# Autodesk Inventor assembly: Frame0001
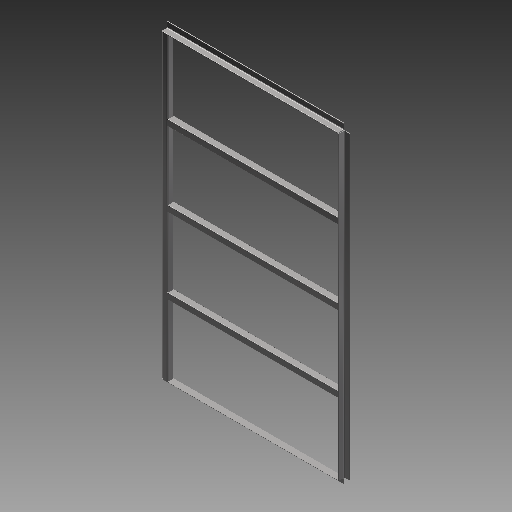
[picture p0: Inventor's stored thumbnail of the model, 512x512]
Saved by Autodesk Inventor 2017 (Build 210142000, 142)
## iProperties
Created: 2020-07
Part Number: Frame0001
Document SubType Name: Assembly
Designer: X
_FrameDoc: Frame Assembly
_Version: 15.0.0
Author: X
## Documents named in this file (16)
- C:\Users\WindowsX\Desktop\brama\skrzydlo_lewe\Frame\Frame0001.iam
- C:\Users\WindowsX\Desktop\brama\skrzydlo_lewe\Frame\Skeleton0001.ipt
- C:\Users\WindowsX\Desktop\brama\skrzydlo_lewe\Frame\PN L40x40x4 00000011.ipt
- PN L35x35x4 00000004.ipt
- C:\Users\WindowsX\Desktop\brama\skrzydlo_lewe\Frame\PN L40x40x4 00000012.ipt
- PN L35x35x4 00000002.ipt
- C:\Users\WindowsX\Desktop\brama\skrzydlo_lewe\Frame\PN L40x40x4 00000013.ipt
- PN L35x35x4 00000003.ipt
- C:\Users\WindowsX\Desktop\brama\skrzydlo_lewe\Frame\PN 40 x 40 x 2 00000016.ipt
- PN 35 x 35 x 2 00000008.ipt
- C:\Users\WindowsX\Desktop\brama\skrzydlo_lewe\Frame\PN 40 x 40 x 2 00000017.ipt
- PN 35 x 35 x 2 00000009.ipt
- C:\Users\WindowsX\Desktop\brama\skrzydlo_lewe\Frame\PN 40 x 40 x 4 00000018.ipt
- PN 40 x 40 x 4 00000018.ipt
- C:\Users\WindowsX\Desktop\brama\skrzydlo_lewe\Frame\PN 40 x 40 x 2 00000019.ipt
- PN 35 x 35 x 2 00000010.ipt
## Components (8 placed, 8 different names)
1. Model odniesienia ramy
2. PN L40x40x4 00000012:1
3. PN L40x40x4 00000013:1
4. PN L40x40x4 00000011:1
5. PN 40 x 40 x 2 00000016:1
6. PN 40 x 40 x 2 00000017:1
7. PN 40 x 40 x 2 00000019:1
8. PN 40 x 40 x 4 00000018:1
